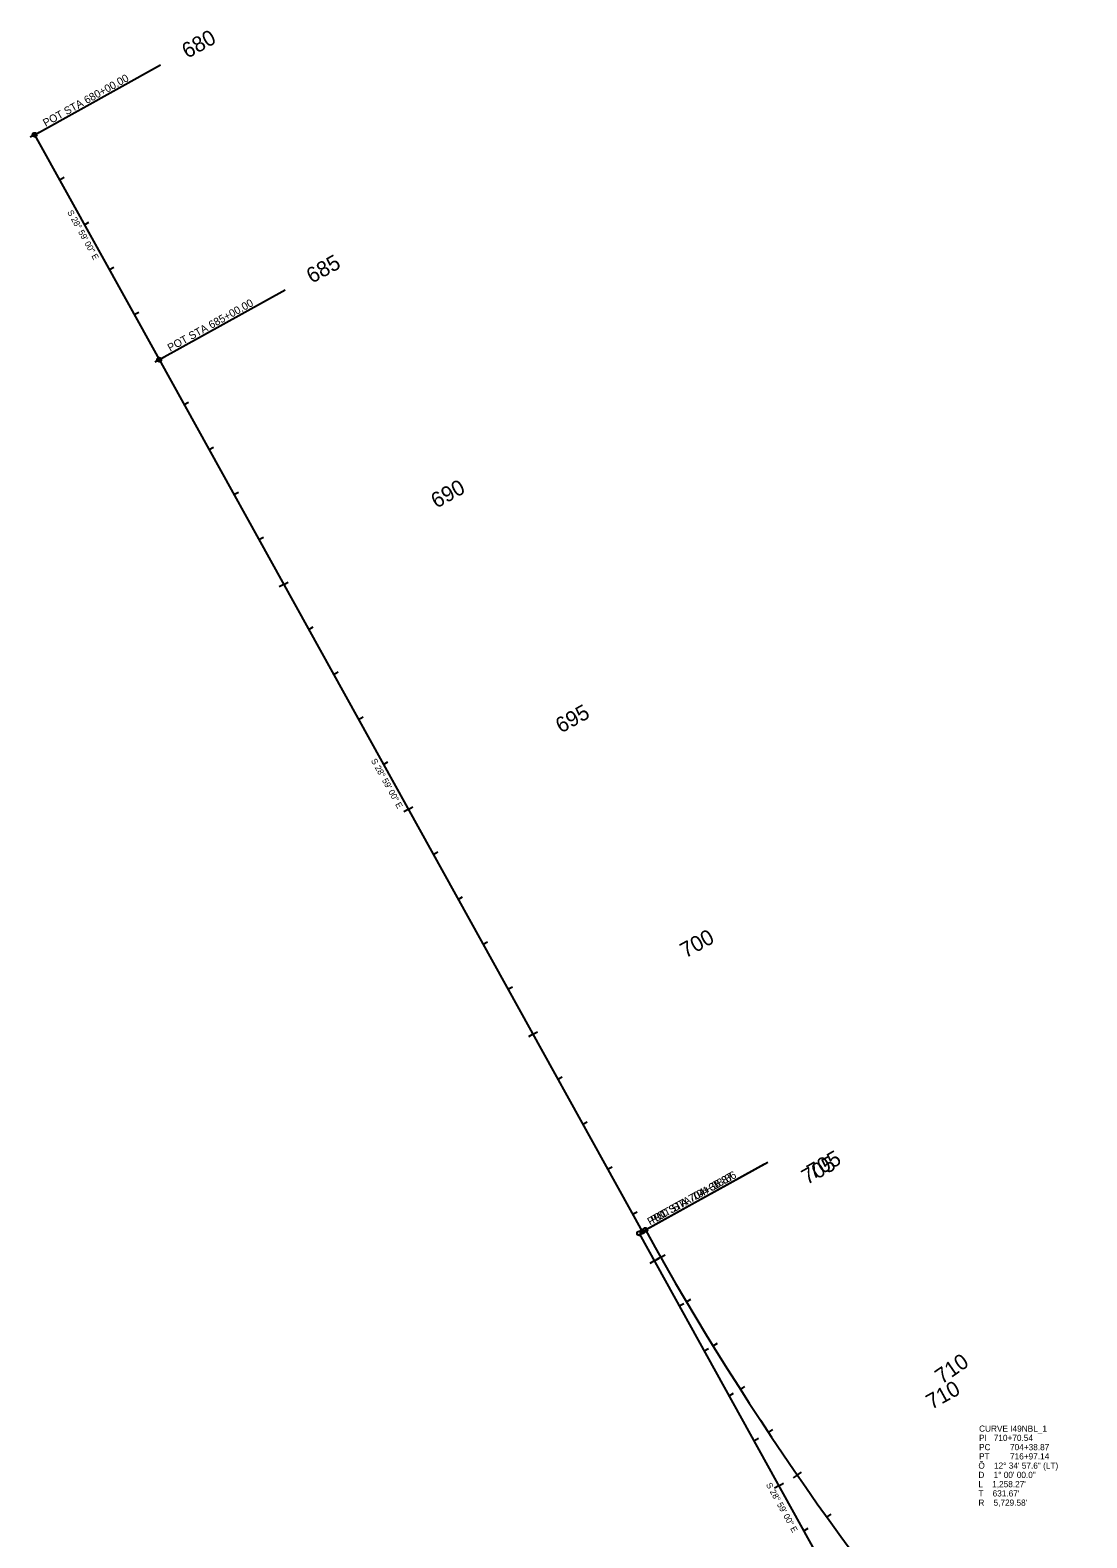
# Model space of a CAD drawing. Extents: x 2819977 to 2827606, y 116785 to 150320.
# Drawn here: x 2820492 to 2822547, y 147388 to 150320 of the extents above; entities that cross this region are included whole.
import ezdxf

# ---------------------------------------------------------------- set-up
doc = ezdxf.new("R2010")
doc.units = 0
for name, color, linetype in [('Modeling-Contours-Major-Existing', 7, 'Continuous'), ('Modeling-Contours-Minor-Existing', 7, 'Continuous'), ('Modeling-Flow Arrows-Existing', 7, 'Continuous'), ('Modeling-Spot-Existing', 7, 'Continuous'), ('Modeling-Triangle Verticies-Existing', 7, 'Continuous')]:
    doc.layers.add(name, color=color, linetype=linetype)

msp = doc.modelspace()

# ---------------------------------------------------------------- linework, layer by layer
at = {"layer": 'Modeling-Contours-Major-Existing'}
for p, q in [((2820500.6, 150117), (2820491.9, 150112.2)), ((2820500.6, 150117), (2820509.4, 150121.9)), ((2820500.6, 150117), (2820742.9, 149679.6)), ((2820549.1, 150029.5), (2820557.8, 150034.4)), ((2820597.5, 149942.1), (2820606.3, 149946.9)), ((2820646, 149854.6), (2820654.7, 149859.4)), ((2820694.4, 149767.1), (2820703.2, 149772)), ((2820742.9, 149679.6), (2820734.1, 149674.8)), ((2820742.9, 149679.6), (2820751.6, 149684.5)), ((2820742.9, 149679.6), (2821682.4, 147983.6)), ((2820791.3, 149592.2), (2820800.1, 149597)), ((2820839.8, 149504.7), (2820848.5, 149509.5)), ((2820888.3, 149417.2), (2820897, 149422.1)), ((2820936.7, 149329.7), (2820945.5, 149334.6)), ((2820985.2, 149242.3), (2820976.4, 149237.4)), ((2820985.2, 149242.3), (2820993.9, 149247.1)), ((2821033.6, 149154.8), (2821042.4, 149159.6)), ((2821082.1, 149067.3), (2821090.8, 149072.2)), ((2821130.5, 148979.8), (2821139.3, 148984.7)), ((2821179, 148892.4), (2821187.7, 148897.2)), ((2821227.4, 148804.9), (2821218.7, 148800)), ((2821227.4, 148804.9), (2821236.2, 148809.7)), ((2821275.9, 148717.4), (2821284.6, 148722.3)), ((2821324.4, 148629.9), (2821333.1, 148634.8)), ((2821372.8, 148542.5), (2821381.6, 148547.3)), ((2821421.3, 148455), (2821430, 148459.8)), ((2821469.7, 148367.5), (2821461, 148362.7)), ((2821469.7, 148367.5), (2821478.5, 148372.3)), ((2821518.2, 148280), (2821526.9, 148284.9)), ((2821566.6, 148192.6), (2821575.4, 148197.4)), ((2821615.1, 148105.1), (2821623.8, 148109.9)), ((2821663.5, 148017.6), (2821672.3, 148022.4)), ((2821676.3, 147980.2), (2822547.2, 146407.9)), ((2821705.9, 147926.7), (2821697.1, 147921.9)), ((2821705.9, 147926.7), (2821714.6, 147931.6)), ((2821754.3, 147839.3), (2821763.1, 147844.1)), ((2821802.8, 147751.8), (2821811.5, 147756.6)), ((2821851.2, 147664.3), (2821860, 147669.2)), ((2821899.7, 147576.8), (2821908.4, 147581.7)), ((2821948.2, 147489.4), (2821939.4, 147484.5)), ((2821948.2, 147489.4), (2821956.9, 147494.2)), ((2821996.6, 147401.9), (2822005.4, 147406.7))]:
    msp.add_line(p, q, dxfattribs=at)
at = {"layer": 'Modeling-Contours-Minor-Existing'}
for p, q in [((2820504.1, 150119), (2820745.5, 150252.7)), ((2820746.4, 149681.6), (2820987.8, 149815.3)), ((2821679.8, 147982.1), (2821920.1, 148115.3)), ((2821685.9, 147985.5), (2821926.8, 148119))]:
    msp.add_line(p, q, dxfattribs=at)
for centre in [(2820500.6, 150117), (2820742.9, 149679.6), (2821676.3, 147980.2), (2821682.4, 147983.6)]:
    msp.add_circle(centre, 4, dxfattribs=at)
at = {"layer": 'Modeling-Flow Arrows-Existing'}
for p, q in [((2821718.4, 147933.7), (2821709.7, 147928.7)), ((2821718.4, 147933.7), (2821727.1, 147938.6)), ((2821768.5, 147847.2), (2821777.2, 147852.3)), ((2821820.2, 147761.5), (2821828.7, 147766.8)), ((2821873.3, 147676.8), (2821881.8, 147682.2)), ((2821927.9, 147593), (2821936.3, 147598.6)), ((2821984, 147510.2), (2821975.8, 147504.6)), ((2821984, 147510.2), (2821992.2, 147515.9)), ((2822041.5, 147428.4), (2822049.6, 147434.2))]:
    msp.add_line(p, q, dxfattribs=at)
msp.add_arc((2826700.5, 150763.3), 5729.6, 208.98347, 221.56614, dxfattribs=at)
at = {"layer": 'Modeling-Spot-Existing'}
msp.add_line((2821692, 147988.9), (2821919.2, 148114.8), dxfattribs=at)
msp.add_circle((2821688.5, 147987), 4, dxfattribs=at)

# ---------------------------------------------------------------- texts
at = {"layer": 'Modeling-Contours-Major-Existing'}
for s, p in [(' 680', (2820787.8, 150259)), (' 685', (2821030.1, 149821.6)), (' 690', (2821272.4, 149384.2)), (' 695', (2821514.6, 148946.8)), (' 700', (2821756.9, 148509.4)), (' 705', (2821993.1, 148068.7)), (' 710', (2822235.3, 147631.3))]:
    msp.add_text(s, height=30, rotation=28.9835, dxfattribs=at).set_placement(p)
at = {"layer": 'Modeling-Contours-Minor-Existing'}
for s, height, rotation, p in [('POT STA 680+00.00', 15, 28.9835, (2820521.9, 150132.2)), ('S 28%%d 59\' 00" E', 12, 298.9835, (2820563.5, 149966.4)), ('POT STA 685+00.00', 15, 28.9835, (2820764.2, 149694.9)), ('S 28%%d 59\' 00" E', 12, 298.9835, (2821154.4, 148899.7)), ('POT STA 704+38.87', 15, 28.9835, (2821697.5, 147995.4)), ('POT STA 704+38.86', 15, 28.9835, (2821703.7, 147998.8)), ('S 28%%d 59\' 00" E', 12, 298.9835, (2821922.7, 147491.4))]:
    msp.add_text(s, height=height, rotation=rotation, dxfattribs=at).set_placement(p)
at = {"layer": 'Modeling-Flow Arrows-Existing'}
for s, rotation, p in [(' 705', 29.5948, (2822004.1, 148078.7)), (' 710', 34.5948, (2822255.9, 147679.6))]:
    msp.add_text(s, height=30, rotation=rotation, dxfattribs=at).set_placement(p)
at = {"layer": 'Modeling-Spot-Existing'}
msp.add_text('PC STA 704+38.87', height=15, rotation=28.9835, dxfattribs=at).set_placement((2821709.8, 148002.2))
at = {"layer": 'Modeling-Triangle Verticies-Existing'}
for s, p in [('CURVE I49NBL_1', (2822337.6, 147594.5)), ('PI   710+70.54', (2822337.6, 147576.5)), ('PC', (2822337.6, 147558.5)), ('704+38.87', (2822397.8, 147558.5)), ('Õ    12%%d 34\' 57.6" (LT)', (2822336.3, 147522.5)), ('PT', (2822337.6, 147540.5)), ('716+97.14', (2822397.8, 147540.5)), ('D    1%%d 00\' 00.0"', (2822336.3, 147504.5)), ("T    631.67'", (2822336.3, 147468.5)), ("L    1,258.27'", (2822336.3, 147486.5)), ("R    5,729.58'", (2822336.3, 147450.5))]:
    msp.add_text(s, height=12, dxfattribs=at).set_placement(p)

doc.saveas('drawing.dxf')
